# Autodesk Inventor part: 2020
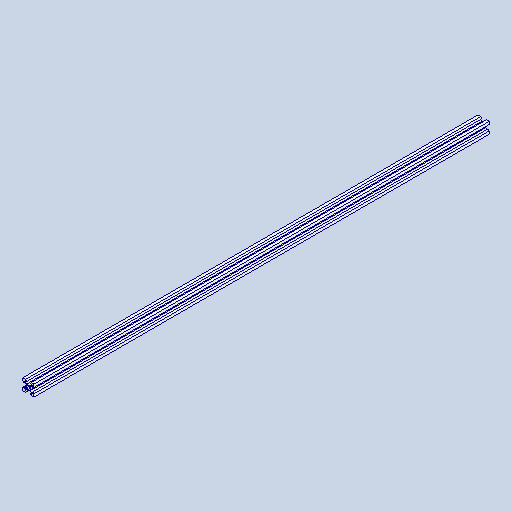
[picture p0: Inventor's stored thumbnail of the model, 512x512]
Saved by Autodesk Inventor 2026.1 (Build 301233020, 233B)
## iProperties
Created: 2024-09
Part Number: 2020
Material: Alluminio 6061
Document SubType Name: Modeling
Designer: hp
Density: 2.7 g/cm^3
Appearance: Default
Author: hp
Revision Number: ANY
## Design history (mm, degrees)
node "Solido1"
sketch "Sketch3"
  geometry: 2 further points
hole "Hole3" sketch "Sketch3" at (32.222, -3.027), (16.972, -3.027) diameter "d14" = 4.5; stored, may be unused: countersink angle "d18" = 90 deg, drill point angle "d20" = 0 deg; dims "d15" = 6, "d16" = 4, "d17" = 2, "d19" = 8
sketch "Sketch6"
  geometry: 2 further points
hole "Hole6" sketch "Sketch6" at (797, 3.053), (810, 3.053) diameter "d35" = 4.5; stored, may be unused: countersink angle "d39" = 90 deg, drill point angle "d41" = 0 deg; dims "d36" = 6, "d37" = 4, "d38" = 2, "d40" = 8
sketch "Sketch7"
  geometry: 2 further points
hole "Hole7" sketch "Sketch7" at (93.5, -3.027), (109.5, -3.027) diameter "d42" = 3.4; stored, may be unused: countersink angle "d46" = 90 deg, drill point angle "d48" = 0 deg; dims "d43" = 6, "d44" = 4, "d45" = 2, "d47" = 8
sketch "Sketch8"
  geometry: 4 further points
hole "Hole8" sketch "Sketch8" at (748, 3.003), (764, 3.003), (64, 3.003), (80, 3.003) diameter "d49" = 4.5; stored, may be unused: countersink angle "d53" = 90 deg, drill point angle "d55" = 0 deg; dims "d50" = 6, "d51" = 4, "d52" = 2, "d54" = 8
body "Solid1"
